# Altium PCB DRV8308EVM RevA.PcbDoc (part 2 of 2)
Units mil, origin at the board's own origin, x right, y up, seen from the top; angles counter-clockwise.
Board outline 4724.41 x 2952.76 mil, 2 copper layers (Top Layer, Bottom Layer), stack 62 mil thick; 110 components, 81 nets, 346 pads, 592 vias.
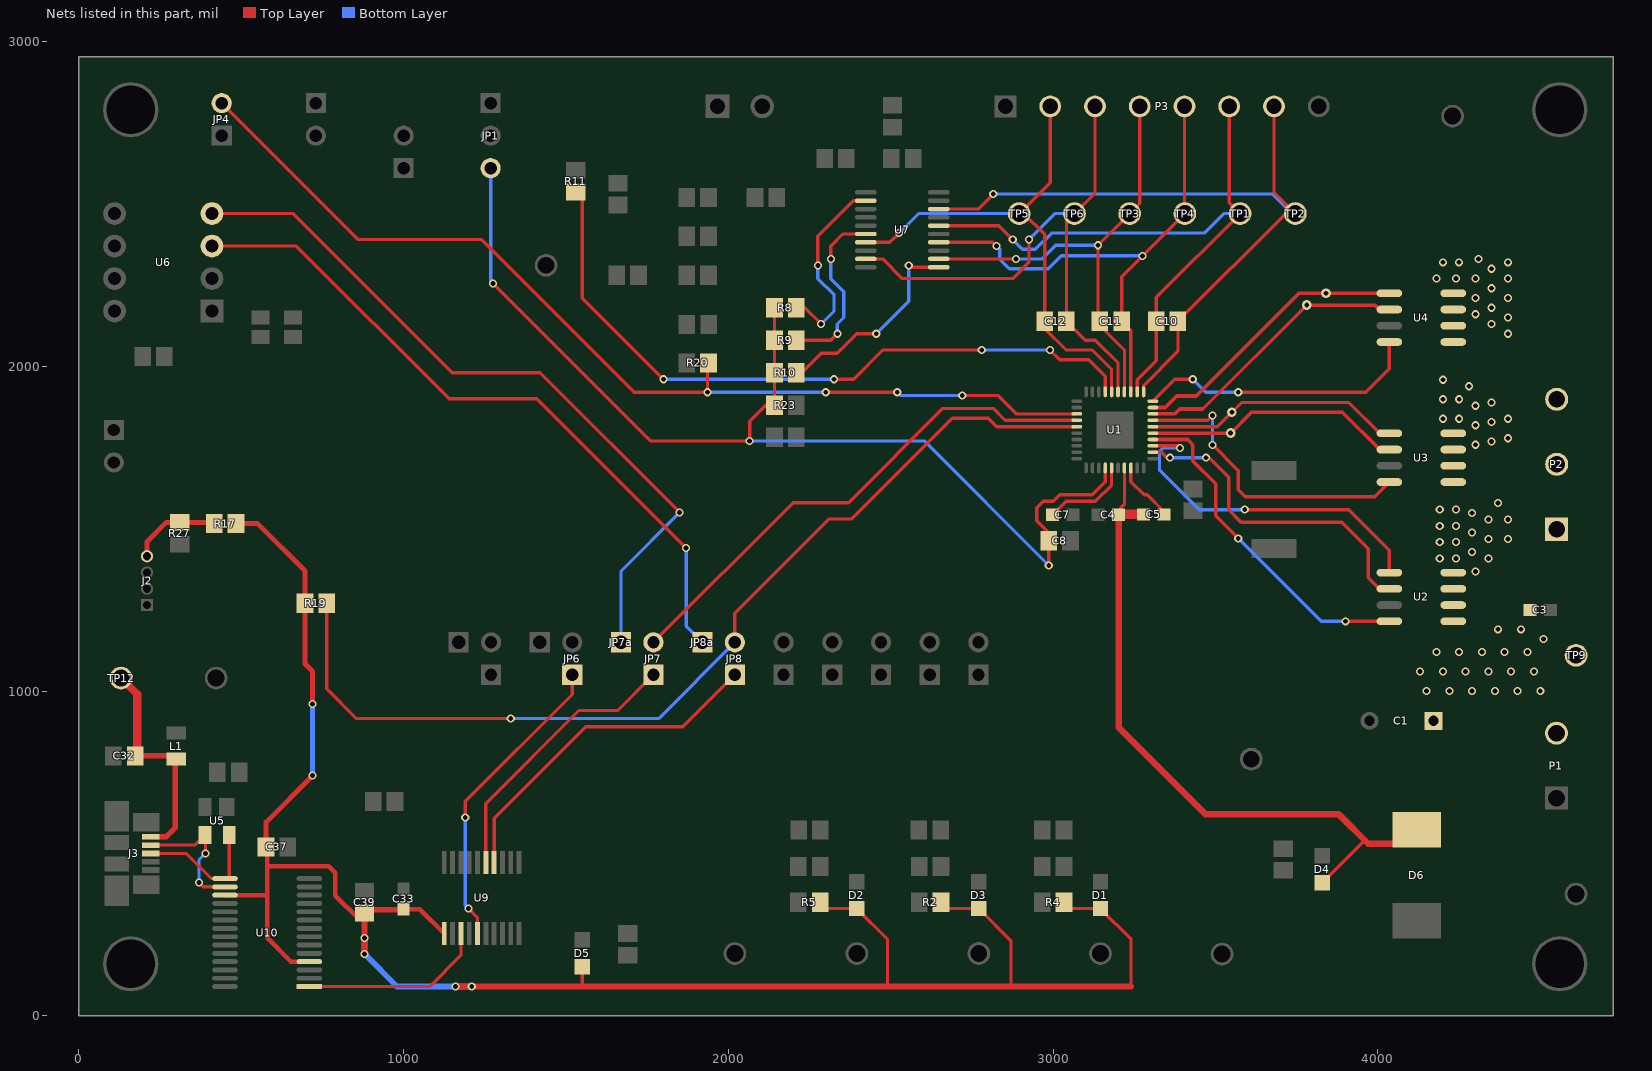
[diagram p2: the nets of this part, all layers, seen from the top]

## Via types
v1: diameter 25, hole 15, Top Layer to Bottom Layer, tented both sides, 582 vias
v2: diameter 25, hole 15, Top Layer to Bottom Layer, tented bottom, 5 vias
v3: diameter 30, hole 15, Top Layer to Bottom Layer, tented bottom, 4 vias
v4: diameter 35, hole 15, Top Layer to Bottom Layer, tented both sides, 1 vias

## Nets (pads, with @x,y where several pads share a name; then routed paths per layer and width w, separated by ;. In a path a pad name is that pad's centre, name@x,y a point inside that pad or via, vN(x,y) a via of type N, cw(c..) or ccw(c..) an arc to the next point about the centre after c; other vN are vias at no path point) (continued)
SCS_MSP430: JP6.1 U9.5 | length 934.6
  Top Layer w10: v1(1190,610) 1190,660 1519.35,989.35 JP6.1@1519.35,1050 ; v1(1200,330) 1227.6,302.4 U9.5@1227.6,253.3
  Bottom Layer w10: 1190,340 v1(1190,610)
SDATAI: JP7.2 U1.14 | length 1616.8
  Top Layer w10: JP7.2@1769.35,1150 2199.35,1580 2370,1580 2660,1870 2815.23,1870 2851.69,1833.54 U1.14@3072.78,1833.54
SDATAI_EEPROM: JP7a.1 U6.4 | length 2295.9
  Top Layer w10: U6.4@410,2470 660,2470 1150,1980 1420,1980 v1(1850,1550)
  Bottom Layer w10: JP7a.1@1669.35,1150 1669.35,1369.35 v1(1850,1550)
SDATAI_MSP430: JP7.1 U9.15 | length 861.4
  Top Layer w10: U9.15@1253.3,472.3 1253.3,653.3 1540,940 1659.35,940 JP7.1@1769.35,1050
SDATAO: JP8.2 R19.1 U1.15 | length 3057.4
  Top Layer w10: R19.1@763.46,1270 763.46,1006.54 855,915 v1(1330,915) ; JP8.2@2020,1150 2020,1240 2310,1530 2380,1530 2690,1840 2800,1840 2826.14,1813.86 U1.15@3072.78,1813.86
  Bottom Layer w10: v1(1330,915) 1785,915 JP8.2@2020,1150
SDATAO_EEPROM: JP8a.1 U6.3 | length 2155.9
  Top Layer w10: U6.3@410,2370 670,2370 1140,1900 1410,1900 v1(1870,1440)
  Bottom Layer w10: v1(1870,1440) 1870,1200 JP8a.1@1920,1150
SDATAO_MSP430: JP8.1 U9.14 | length 1060.2
  Top Layer w10: U9.14@1278.9,472.3 1278.9,608.55 1560.35,890 1860,890 JP8.1@2020,1050
SMODE: JP4.2 R20.2 U1.13 | length 3115.6
  Top Layer w10: JP4.2@440,2810 860,2390 1240,2390 1710,1920 v1(1935.51,1920) R20.2@1935.51,2006.54 ; v1(2300,1920) v1(2520,1920) ; v1(2720,1910) 2830,1910 2886.77,1853.23 U1.13@3072.78,1853.23
  Bottom Layer w10: v1(1935.51,1920) v1(2300,1920) ; v1(2520,1920) 2530,1910 v1(2720,1910)
TX: U9.3 U10.1 | length 573.2
  Top Layer w10: U10.1@710,90 1080,90 1176.4,186.4 U9.3@1176.4,253.3
U: P2.1 U1.33 U2.1 U2.5 U2.6 | length 1088.9
  Top Layer w10: v1@3383.84,1754.8 v1(3390.22,1748.43)
  Top Layer w11: U1.33@3307.03,1754.8 v1@3383.84,1754.8 ; v2(3590,1558.43) 3910.22,1558.43 4035.1,1433.54 U2.1@4035.1,1364.63
  Bottom Layer w10: v1(3390.22,1748.43) 3338.43,1748.43 3327.7,1737.7 3327.7,1680 3449.28,1558.43 v2(3590,1558.43)
U+: R8.2 U7.2 | length 597.7
  Top Layer w10: R8.2@2208.98,2180 2235.51,2180 v1(2285.51,2130) ; v1(2275.51,2310) 2275.51,2400 2385.08,2509.57 U7.2@2423.31,2509.57
  Bottom Layer w10: v1(2275.51,2310) 2275.51,2270 2325.51,2220 2325.51,2170 v1(2285.51,2130)
UH+: C10.2 P3.7 TP2.1 U1.1 U7.18 | length 2258.6
  Top Layer w10: U7.18@2647.72,2483.98 2769.49,2483.98 v1(2815.51,2530) ; U1.1@3278.49,1921.14 3278.49,1940.3 3384.23,2046.04 C10.2@3384.23,2138.54 3715.69,2470 TP2.1@3745.51,2470 3680,2535.51 P3.7@3680,2800
  Bottom Layer w10: v1(2815.51,2530) 3675.51,2530 3735.51,2470 TP2.1@3745.51,2470
UH-: C10.1 P3.6 TP1.1 U1.2 U7.16 | length 2027.4
  Top Layer w10: U7.16@2647.72,2432.8 2832.72,2432.8 v1(2875.51,2390) ; U1.2@3258.8,1921.14 3258.8,1958.8 3317.3,2017.3 C10.1@3317.3,2138.54 3317.3,2211.79 TP1.1@3575.51,2470 3542.2,2503.31 P3.6@3542.2,2800
  Bottom Layer w10: v1(2875.51,2390) 2905.51,2360 2945.51,2360 2995.51,2410 3465.51,2410 3525.51,2470 TP1.1@3575.51,2470
UHS_GATE: U1.32 U2.2 | length 1013.5
  Top Layer w10: v1@3350.22,1718.43 v1(3360.22,1718.43) ; U2.2@4004.02,1314.63 U2.2@4035.1,1314.63
  Top Layer w11: U1.32@3307.03,1735.12 3333.53,1735.12 v1@3350.22,1718.43 ; v2(3470.22,1718.43) 3480.22,1718.43 3540.22,1658.43 3540.22,1558.43 3578.65,1520 3888.65,1520 3970.22,1438.43 3970.22,1348.43 U2.2@4004.02,1314.63
  Bottom Layer w11: v1(3360.22,1718.43) v2(3470.22,1718.43)
ULS_GATE: U1.34 U2.4 | length 1047
  Top Layer w11: U1.34@3307.03,1774.49 3414.16,1774.49 3430.22,1758.43 3430.22,1708.43 3500.22,1638.43 3500.22,1539.78 v2(3570,1470) ; v1(3900,1214.63) U2.4@4035.1,1214.63
  Bottom Layer w11: v2(3570,1470) 3825.37,1214.63 v1(3900,1214.63)
USB5V: C32.2 J3.1 L1.1 TP12.1 | length 668.7
  Top Layer w17: C32.2@173.46,800 L1.1@290,800 ; J3.1@221.61,551.18 268.82,551.18 297.64,580 L1.1@297.64,790
  Top Layer w25: TP12.1@130,1040 180,990 C32.2@180,806.54
USBDM: J3.2 U5.3 U10.16 | length 418.8
  Top Layer w10: J3.2@221.61,525.59 357.4,525.59 U5.3@388.5,556.69 ; v1(370,410) 382.91,397.09 U10.16@450.16,397.09 ; v1(390,500) U5.3@390,555.2
  Bottom Layer w10: v1(370,410) 370,480 v1(390,500)
USBDP: J3.3 U5.4 U10.15 | length 394.4
  Top Layer w10: J3.3@221.61,500 330,500 407.32,422.68 U10.15@450.16,422.68 ; U10.15@463.31,422.88 U5.4@463.31,556.69
V: P2.2 U1.36 U3.1 U3.5 U3.6 | length 798.3
  Top Layer w10: U1.36@3307.03,1813.86 3505.66,1813.86 3580.22,1888.43 3910.22,1888.43 4005.22,1793.43 U3.1@4035.1,1793.43
  other v3: 3550.22,1858.43
V3P3: C33.1 C37.2 C39.1 D1.1 D2.1 D3.1 D5.1 R2.2 R4.2 R5.2 R17.2 R19.2 U9.1 U10.4 U10.17 | length 6232.7
  Top Layer w10: 1550,90 D5.1@1550,151.12 ; R5.2@2301.8,330.25 D2.1@2395.59,330.25 2490,235.84 2490,90 ; R2.2@2674.33,330.44 D3.1@2771.11,330.44 2870,231.55 2870,90 ; R4.2@3052.9,330.25 D1.1@3145.59,330.25 3240,235.84 3240,90
  Top Layer w14: U10.17@450.16,371.5 580,371.5 ; C37.2@580,516.54 580,460 ; U10.4@710,166.77 653.23,166.77 580,240 580,371.5 ; C39.1@860,300 790,370 790,440 770,460 580,460 ; C33.1@1000,328.5 1050,328.5 U9.1@1125.2,253.3 ; 580,371.5 580,460
  Top Layer w15: R17.2@484.09,1515.59 550.94,1515.59 696.54,1370 R19.2@696.54,1270 696.54,1083.46 720,1060 v1(720,960) ; C37.2@576.54,520 576.54,596.54 v1(720,740)
  Top Layer w18: v1(880,190) v1(880,240) 880,326.54 C33.1@988.03,326.54 ; v1(1160,90) v1(1210,90) 1550,90 2870,90 3240,90
  Bottom Layer w15: v1(720,740) v1(720,960)
  Bottom Layer w18: v1(880,240) v1(880,190) 980,90 v1(1210,90)
V3P3X: J2.4 R17.1 R27.1 | length 273.2
  Top Layer w15: J2.4@210,1415 210,1460 269.06,1519.06 R27.1@310.63,1519.06 R17.1@413.7,1519.06
V+: R9.2 U7.6 | length 552.9
  Top Layer w10: R9.2@2208.98,2080 2315.51,2080 v1(2335.51,2100) ; v1(2315.51,2330) 2315.51,2370 2352.72,2407.2 U7.6@2423.31,2407.2
  Bottom Layer w10: v1(2315.51,2330) 2315.51,2270 2355.51,2230 2355.51,2150 2335.51,2130 v1(2335.51,2100)
VCP: C5.1 U1.28 | length 182.5
  Top Layer w10: U1.28@3239.12,1686.89 3239.12,1644.8 3279.91,1604.02 3290.08,1604.02 C5.1@3341.4,1552.7
VH+: C11.2 P3.5 TP4.1 U1.3 U7.14 | length 1667.3
  Top Layer w10: U7.14@2647.72,2381.61 2813.9,2381.61 v1(2825.51,2370) ; U1.3@3239.12,1921.14 3239.12,2110.35 C11.2@3210.92,2138.54 3210.92,2275.41 v1(3275.51,2340) TP4.1@3405.51,2470 3404.41,2471.1 P3.5@3404.41,2800
  Bottom Layer w10: v1(2825.51,2370) 2835.51,2360 2835.51,2330 2865.51,2300 2985.51,2300 3025.51,2340 v1(3275.51,2340)
VH-: C11.1 P3.4 TP3.1 U1.4 U7.12 | length 1444.6
  Top Layer w10: U7.12@2655.51,2330.43 2885.08,2330.43 v1(2885.51,2330) ; C11.1@3138.05,2144.49 v1(3138.05,2372.54) TP3.1@3235.51,2470 3266.61,2501.1 P3.4@3266.61,2800 ; C11.1@3144,2125.44 3219.43,2050 U1.4@3219.43,1921.14
  Bottom Layer w10: v1(2885.51,2330) 2965.51,2330 3008.05,2372.54 v1(3138.05,2372.54)
VHS_GATE: U1.35 U3.2 | length 802.3
  Top Layer w10: U3.2@4005.22,1743.43 U3.2@4035.1,1743.43
  Top Layer w11: U1.35@3307.03,1794.17 v3(3546.51,1794.17) 3610.77,1858.43 3890.22,1858.43 U3.2@4005.22,1743.43
VINT: C7.1 U1.25 | length 272.3
  Top Layer w10: C7.1@2998.41,1542.7 3039.73,1584.02 3129.91,1584.02 3180.06,1634.17 U1.25@3180.06,1686.89
VLS_GATE: U1.37 U3.4 | length 943.8
  Top Layer w10: v2(3490.77,1757.88) 3570,1678.65
  Top Layer w11: U1.37@3307.03,1833.54 3475.89,1833.54 v1(3490.77,1848.43) ; 3570,1678.65 3570,1620 3591.57,1598.43 3990.1,1598.43 U3.4@4035.1,1643.43
  Bottom Layer w10: v2(3490.77,1757.88) v1(3490.77,1848.43)
VM: C1.1 C3.1 C4.1 C5.2 D4.1 D6.2 P1.2 TP9.1 U1.27 U2.7 U2.8 U3.7 U3.8 U4.7 U4.8 | length 2089.9
  Top Layer w10: C4.1@3201.4,1542.7 3202.72,1544.02 C4.1@3215.43,1556.73 ; C4.1@3201.4,1556.46 3219.43,1574.49 U1.27@3219.43,1686.89 ; D4.1@3828.24,409.8 3959.22,540.78
  Top Layer w20: C4.1@3201.4,1542.7 3201.4,888.6 3470,620 3880,620 3970,530 D6.2@4070,530
  Top Layer w30: C4.1@3202.72,1544.02 C5.2@3278.41,1544.02
  other v1: 4150,1000 4220,1000 4290,1000 4360,1000 4430,1000 4500,1000 4130,1060 4200,1060 4270,1060 4340,1060 4410,1060 4480,1060 4180,1120 4250,1120 4320,1120 4390,1120 4460,1120 4510,1160 4370,1190 4440,1190 4300.22,1368.43 4190.22,1408.43 4240.22,1408.43 4340.22,1408.43 4290.22,1428.43 4190.22,1458.43 4240.22,1458.43 4340.22,1468.43 4400.22,1468.43 4290.22,1488.43 4190.22,1508.43 4240.22,1508.43 4340.22,1528.43 4400.22,1528.43 4290.22,1548.43 4190.22,1558.43 4240.22,1558.43 4370.22,1578.43 4300.22,1758.43 4350.22,1768.43 4400.22,1778.43 4300.22,1818.43 4350.22,1828.43 4200.22,1838.43 4250.22,1838.43 4400.22,1838.43 4300.22,1878.43 4350.22,1888.43 4200.22,1898.43 4250.22,1898.43 4280.22,1938.43 4200.22,1958.43 4400,2100 4350,2130 4400,2150 4300,2160 4350,2180 4300,2210 4400,2210 4350,2240 4180,2270 4240,2270 4300,2270 4400,2270 4350,2300 4200,2320 4250,2320 4400,2320 4310,2330
VREG: C8.2 JP1.3 R8.1 R9.1 R10.1 R23.2 U1.24 | length 3332
  Top Layer w10: v1(1275,2255) 1760,1770 v1(2065.51,1770) 2065.51,1830 2115.51,1880 R23.2@2142.05,1880 R10.1@2142.05,1980 ; R10.1@2142.05,1996.54 R9.1@2142.05,2080 R8.1@2142.05,2180 ; v1(2986.44,1386.44) C8.2@2986.44,1462.7 ; C8.2@2992.11,1481.81 2949.91,1524.02 2949.91,1564.02 2969.91,1584.02 2999.91,1584.02 3019.91,1604.02 3119.91,1604.02 3160.38,1644.49 U1.24@3160.38,1686.89
  Bottom Layer w10: JP1.3@1268.03,2610 1268.03,2261.97 v1(1275,2255) ; v1(2065.51,1770) 2602.88,1770 v1(2986.44,1386.44)
VSW: R11.2 U1.7 | length 2159.5
  Top Layer w10: R11.2@1550,2536.54 1550,2210 v1(1800,1960) ; v1(2325.51,1960) 2385.51,1960 2475.51,2050 v1(2780,2050) ; v1(2990,2050) 3020,2020 3110,2020 3160.38,1969.62 U1.7@3160.38,1921.14
  Bottom Layer w10: v1(1800,1960) v1(2325.51,1960) ; v1(2780,2050) v1(2990,2050)
W: P2.3 U1.39 U4.1 U4.5 U4.6 | length 873.8
  Top Layer w11: U1.39@3307.03,1872.91 3344.71,1872.91 3380.22,1908.43 3440.77,1908.43 3756.97,2224.63 3880.22,2224.63 U4.1@4035.1,2224.63
  other v3: 3840,2224.63
W+: R10.2 U7.11 | length 635
  Top Layer w10: R10.2@2208.98,1980 2225.51,1980 2285.51,2040 2335.51,2040 2395.51,2100 v1(2455.51,2100) ; v1(2555.51,2310) 2560.67,2304.84 U7.11@2640.67,2304.84
  Bottom Layer w10: v1(2455.51,2100) 2555.51,2200 v1(2555.51,2310)
WH+: C12.2 P3.3 TP6.1 U1.5 U7.9 | length 1790
  Top Layer w10: U7.9@2423.31,2330.43 2475.08,2330.43 2535.51,2270 2875.51,2270 2925.51,2320 v1(2925.51,2390) ; P3.3@3128.82,2800 3128.82,2533.31 TP6.1@3065.51,2470 3040.92,2445.41 C12.2@3040.92,2138.54 3099.47,2080 3130,2080 3199.75,2010.25 U1.5@3199.75,1921.14
  Bottom Layer w10: v1(2925.51,2390) 3005.51,2470 TP6.1@3065.51,2470
WH-: C12.1 P3.2 TP5.1 U1.6 U7.7 | length 1577.9
  Top Layer w10: U7.7@2423.31,2381.61 2497.13,2381.61 v1(2525.51,2410) ; C12.1@2974,2116 3040,2050 3120,2050 3180.06,1989.94 U1.6@3180.06,1921.14 ; C12.1@2974,2138.54 2974,2406 2910,2470 TP5.1@2895.51,2470 2991.02,2565.51 P3.2@2991.02,2800
  Bottom Layer w10: v1(2525.51,2410) 2585.51,2470 TP5.1@2895.51,2470
WHS_GATE: U1.38 U4.2 | length 872.6
  Top Layer w10: 3460.77,1868.43 v3(3780.77,2188.43) ; U4.2@4004.02,2174.63 U4.2@4035.1,2174.63
  Top Layer w11: U1.38@3307.03,1853.23 3375.03,1853.23 3390.22,1868.43 3460.77,1868.43 ; v3(3780.77,2188.43) 3990.22,2188.43 U4.2@4004.02,2174.63
WLS_GATE: U1.40 U4.4 | length 884.6
  Top Layer w11: U1.40@3307.03,1892.6 3374.43,1960 v1(3430,1960) ; v2(3570,1920) 3962.34,1920 4035.1,1992.76 U4.4@4035.1,2074.63
  Bottom Layer w11: v1(3430,1960) 3470,1920 v2(3570,1920)
pads on no net: J3.4 U6.7 U7.3 U7.5 U7.15 U7.17 U9.2 U9.6 U10.2 U10.3 U10.6 U10.8 U10.9 U10.10 U10.11 U10.12 U10.13 U10.14 U10.19 U10.22 U10.23 U10.24 U10.27 U10.28

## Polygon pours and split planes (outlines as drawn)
GND on Bottom Layer "Bottom GND plane" (solid, remove dead copper, pour order 7): 0,0 4724.41,0 4724.41,2952.76 0,2952.76
GND on Top Layer "Top GND plane" (solid, remove dead copper, pour order 4): 0,0 4724.41,0 4724.41,2952.76 0,2952.76

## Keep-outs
Keep-Out Layer:
  lines w10: -5,0 ccw(c0,0) 0,-5 ; -5,0 ccw(c0,0) 0,-5 ; -5,0 ccw(c0,0) 0,-5 ; -5,0 ccw(c0,0) 0,-5 ; -5,0 ccw(c0,0) 0,-5 ; -5,0 ccw(c0,0) 0,-5
  lines w19.68: -9.84,0 ccw(c0,0) 0,-9.84 ; -9.84,0 ccw(c0,0) 0,-9.84 ; -9.84,0 -9.84,2952.76 ; -9.84,2952.76 cw(c0,2952.76) 0,2962.6 ; -9.84,2952.76 cw(c0,2952.76) 0,2962.6 ; 0,-9.84 4724.41,-9.84 ; 0,2962.6 4724.41,2962.6 ; 4724.41,-9.84 ccw(c4724.41,0) 4734.25,0 ; 4724.41,-9.84 ccw(c4724.41,0) 4734.25,0 ; 4724.41,2962.6 cw(c4724.41,2952.76) 4734.25,2952.76 ; 4724.41,2962.6 cw(c4724.41,2952.76) 4734.25,2952.76 ; 4734.25,0 4734.25,2952.76
  text ".Layer_Name" at 577,-858.49 h60

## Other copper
Top Layer:
  region net VM: 4258.86,2163.3 4414.81,2075.58 4413.49,2349.24 4349,2350.75 4244.77,2349.86 4163.52,2349.26 4163.52,2231.62 4199.93,2164.7
  region net VM: 4041.87,516.13 4195.5,515.26 4287.5,694.06 4411.95,786.23 4587.06,825.21 4649.24,1091.74 4649.22,1136.61 4510.04,1206.89 4483.97,1236.82 4438.43,1278.55 4346.86,1202.47 4267.29,1168.03 4164.67,1167.83 4114.24,1117.03 4113.3,942.03 4096.73,800.79 4051.76,676.12
  region net W: 4006.57,2234.88 4122.9,2234.88 4163.62,2185.35 4181.8,2156.34 4193.63,2143.67 4205.47,2136.17 4263.44,2135.42 4263.44,2061.48 4172.2,2061.48 4120.44,2136.77 4096.83,2174.8 4085.29,2195.6 4067.48,2210.49 4002.68,2211.96
  region net V: 4006.57,1804.88 4122.9,1804.88 4163.62,1755.35 4181.8,1726.34 4193.63,1713.67 4205.47,1706.17 4263.44,1705.42 4263.67,1629.29 4176.64,1625.49 4120.44,1706.77 4096.83,1744.8 4085.29,1765.6 4067.48,1780.49 4002.68,1781.96
  region net U: 4006.57,1374.88 4122.9,1374.88 4163.62,1325.35 4181.8,1296.34 4193.63,1283.67 4205.47,1276.17 4263.44,1275.42 4263.44,1201.48 4172.2,1201.48 4120.44,1276.77 4096.83,1314.8 4085.29,1335.6 4067.48,1350.49 4002.68,1351.96
  region net VM: 4205.95,1732.88 4193.09,1741.46 4163.79,1790.41 4164.05,2011.1 4414.71,1893.78 4415.64,1763.04 4263.18,1732.11
  region net VM: 4240.75,1302.54 4264.65,1302.54 4414.82,1460.67 4414.78,1603.51 4164.12,1590.95 4163.85,1356.84 4198.71,1303.94
  region net ISENSE: 4029.45,1253.44 4029.19,1253.18 4000.98,1253.18 3967.35,1235.32 3927.88,1235.32 3905.08,1242.91 3851.83,1247.15 3804.11,1303.16 3777.51,1351.69 3772.48,1371.05 3772.48,1492.98 3873.95,1492.98 3926.33,1446.98 3935.81,1439.7 3941.38,1432.57 3944.07,1408.69 3943.42,1372.54 3951.92,1336.28 3973.6,1302.25 4007.37,1276.08
  region net ISENSE: 4007.5,1682.15 3976.85,1664.07 3931.6,1625.35 3784.48,1625.55 3665.48,1625.55 3610,1630 3599.29,1699.74 3597.02,1726.84 3609.18,1804.82 3625.99,1816.21 3870.36,1827.96 3909.21,1808.29 3971.57,1725.3 4008.56,1704.99
  region net ISENSE: 4008.52,2136.21 3974.04,2161.93 3826.03,2161.93 3806.54,2145.65 3790.24,2111.54 3775.45,2048.1 3774.15,1944.05 3949.86,1944.21 3970.64,1965.72 3973.71,2046.8 3979.09,2088.18 3984.66,2097.22 4007.92,2113.22
  region net U: 4256.81,1276.41 4277.94,1286.82 4513.54,1540.16 4594.28,1540.15 4594.26,1455.59 4422.1,1292.23 4351.5,1231.81 4266.02,1186.23 4165.48,1186.82 4164.29,1248.28
  region net V: 4204.53,1703.76 4547.81,1742.82 4594.73,1742.82 4594.73,1658.82 4322.01,1621.72 4176.76,1613.37
  region net W: 4166.5,2057.62 4534.23,1855.38 4595.09,1855.09 4593.75,1930.53 4429.96,2049.16 4262.29,2136.49 4228.44,2137.5 4166.5,2108.04
  text ".Layer_Name" at 577,-858.49 h60
Bottom Layer:
  region net VM: 4163.18,2350 4163.18,1137.74 4414.7,1137.74 4414.7,2350
  region net VM: 4411.06,1257.33 4497.82,1221.76 4545.24,1187.27 4648.69,1136.27 4648.83,1091.15 4617.89,968.85 4594.2,886.44 4585.64,826.27 4135.24,876.39 4114.02,1033.26 4114.59,1117.36 4163.15,1166.7
  region net ISENSE: 4108.01,2262 4153.28,2262.31 4153.52,1189.26 3993.81,1197.63 3967.35,1235.35 3927.72,1235.18 3905.5,1243.32 3851.96,1246.89 3804.73,1302.74 3777.51,1351.81 3772.59,1371.16 3772.34,1571.25 3729.15,1609.96 3611.67,1630.43 3604.13,1665.46 3599.91,1700.36 3597.02,1726.84 3613.63,1810.93 3746.57,1818.3 3771.54,1838.25 3773.85,1888.04 3775.12,2047.77 3790.11,2111.14 3806.53,2145.63 3824.96,2162 3872.06,2162 3898.03,2182.27 3925.39,2260.44
  text ".Layer_Name" at 577,-858.49 h60

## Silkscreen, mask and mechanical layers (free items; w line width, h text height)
Top Overlay:
  text "HALL" at 3907.23,2881.54 h70
  text "FG" at 2193.79,2880.79 h70
  text "INPUT" at 2193.79,2825.68 h70
  text "INPUT" at 3907.24,2825.68 h70
  text "CURRENT" at 1378.03,2745.7 h55
  text "]" at 1338.03,2720 h180
  text "GND" at 4163.51,2652.88 h70
  text "5V" at 1095.16,2639.36 h60
  text "_" at 1941.09,2632.48 h100
  text "]" at 1053.72,2617.55 h180
  text "[" at 1167.04,2617.55 h180
  text "_" at 3015.06,2616.5 h55
  text "_" at 3283.2,2616.5 h55
  text "_" at 3559.94,2616.5 h55
  text "DIFF" at 664.19,2602.79 h70
  text "SMODE" at 327.82,2602.01 h70
  text "HPWR" at 3751.23,2598.8 h50
  text "HGND" at 2790.13,2598.26 h50
  text "W" at 2960.75,2592.42 h60
  text "W" at 3096.86,2592.42 h60
  text "V" at 3243.84,2592.42 h60
  text "V" at 3380.16,2592.42 h60
  text "U" at 3521.27,2592.42 h60
  text "U" at 3655.88,2592.42 h60
  text "+" at 3150.87,2589.61 h70
  text "+" at 3419.22,2589.61 h70
  text "+" at 3694.24,2589.61 h70
  text "+" at 2081.93,2587.35 h100
  text "HALL" at 649.78,2549.76 h70
  text "HALL POWER" at 939.81,2503.74 h70
  text "W" at 4087.75,2258.24 h110
  text "W" at 3788.38,2211.55 h40
  text "GND" at 1372.45,2194.43 h70
  text "WHSG" at 3651.62,2174.59 h40
  text "WLSG" at 3590,1910 h40
  text "V" at 3569.69,1846.05 h40
  text "V" at 4102.19,1826.51 h110
  text "CLKIN" at 166.89,1788.96 h80
  text "VHSG" at 3425.69,1780.4 h40
  text "VLSG" at 3507.16,1743.19 h40
  text "UHSG" at 3487.81,1705.14 h40
  text "GND" at 166.92,1670 h80
  text "U" at 3550.99,1544.55 h40
  text "DRV8308EVM" at 850,1510 h100
  text "ULSG" at 3489.06,1426.59 h40
  text "U" at 4104.59,1400.86 h110
  text "SCLK" at 1286.35,1216 h60 r90
  text "SCS" at 1536.35,1216 h60 r90
  text "SDATAI" at 1786.35,1216 h60 r90
  text "SDATAO" at 2036.35,1216 h60 r90
  text "CLKIN" at 2186.35,1216 h60 r90
  text "BRAKE" at 2336.35,1216 h60 r90
  text "DIR" at 2486.35,1216 h60 r90
  text "ENABLE" at 2636.35,1216 h60 r90
  text "RESET" at 2786.35,1216 h60 r90
  text "USB5V" at 36.41,1109.99 h80
  text "GND" at 346.96,1110 h80
  text "VM" at 4565.23,990.73 h70
  text "EEPROM" at 1186.35,866 h60 r90
  text "MCU" at 1286.35,866 h60 r90
  text "EEPROM" at 1436.35,866 h60 r90
  text "MCU" at 1536.35,866 h60 r90
  text "EEPROM" at 1686.35,866 h60 r90
  text "MCU" at 1786.35,866 h60 r90
  text "EEPROM" at 1936.35,866 h60 r90
  text "MCU" at 2036.35,866 h60 r90
  text "MCU" at 2186.35,866 h60 r90
  text "MCU" at 2336.35,866 h60 r90
  text "MCU" at 2486.35,866 h60 r90
  text "MCU" at 2636.35,866 h60 r90
  text "MCU" at 2789.22,866 h60 r90
  text "GND" at 3543.51,672.11 h70
  text "GND" at 4543.51,450.45 h70
  text "VM" at 3777.05,320 h80
  text "REV.A" at 4240,80 h60
  text "V3P3" at 1463.89,60.94 h80
  text "GND" at 1943.97,60.94 h80
  text "FGOUT" at 2273.72,60.94 h80
  text "FAULTn" at 2637.01,60.94 h80
  text "LOCKn" at 3027.5,60.94 h80
  text "ENABLE" at 3377.19,60 h80
  text ".Layer_Name" at 577,-858.49 h60
Bottom Overlay:
  text ".Layer_Name" at 577,-858.49 h60
Top Paste:
  text ".Layer_Name" at 577,-858.49 h60
Bottom Paste:
  text ".Layer_Name" at 577,-858.49 h60
Top Solder:
  text ".Layer_Name" at 577,-858.49 h60
  text ".Layer_Name" at 577,-858.49 h60
Bottom Solder:
  text ".Layer_Name" at 577,-858.49 h60
Drill Guide:
  text ".Layer_Name" at 577,-858.49 h60
M1 Board Outline:
  the board outline again, w10
  text ".Layer_Name" at 577,-858.49 h60
M2 Board Dimensions:
  rectangle: 124.5,-410.5 499.5,-285.5
  rectangle: -0.5,-285.5 124.5,-160.5
  lines w7: -0.5,-285.5 999.5,-285.5 ; 124.5,-410.5 124.5,-160.5 ; 249.5,-410.5 249.5,-160.5 ; 499.5,-410.5 499.5,-160.5 ; 749.5,-410.5 749.5,-160.5 ; -0.5,-410.5 -0.5,-160.5 999.5,-160.5 999.5,-410.5 -0.5,-410.5
  lines w10: -0.5,-475.5 -0.5,-455.5 ; 59.5,-485.5 -0.5,-465.5 ; 59.5,-445.5 -0.5,-465.5 ; 223.58,-465.5 -0.5,-465.5 ; 775.42,-465.5 999.5,-465.5 ; 939.5,-485.5 999.5,-465.5 ; 939.5,-445.5 999.5,-465.5 ; 999.5,-475.5 999.5,-455.5
  text "1000 (mil)" at 233.58,-501.49 h60
  text ".Layer_Name" at 577,-858.49 h60
M3 3D STEP Top:
  text ".Layer_Name" at 577,-858.49 h60
M4 3D STEP Bottom:
  text ".Layer_Name" at 577,-858.49 h60
M5 Assembly Top:
  lines w10: -292,-930.17 6308,-930.17 ; -292,-726.83 6310,-726.83 ; -292,-523.5 -292,-1133.5 3713,-1133.5 6310,-1133.5 6310,-523.5 -291.5,-523.5 -291.5,-1133.5 1284,-1133.5 ; 2173,-1133.5 2173,-523.5 ; 3440,-726.83 3440,-523.5 ; 4280,-726.83 4280,-523.5 ; 4902,-1140 4902,-937.17
  text "COMPONENTS MARKED 'DNP' SHOULD NOT BE POPULATED." at 1153.5,-318.5 h60
  text "ASSEMBLY VARIANT:" at 1153,-434 h60
  text ".VariantName" at 2189,-434 h60
  text "PCB VIEWED FROM TOP SIDE" at -228.5,-655.67 h60
  text "BOARD #:" at 2248,-655.67 h60
  text ".PRJ_Number" at 2793.5,-655.67 h60
  text "REV:" at 3638,-655.67 h60
  text ".PCB_Rev" at 3929.5,-655.67 h60
  text "SVN REV:" at 4476,-655.67 h60
  text ".VersionControl_RevNumber" at 4982,-655.67 h60
  text "IGNORE ->" at -228.5,-858.49 h60
  text "PLOT NAME =" at -228.5,-1064.34 h60
  text ".plot_File_Name" at 577,-1064.34 h60
  text "GENERATED    :" at 2250,-1064.34 h60
  text ".Print_Date" at 3119.5,-1064.34 h60
  text ".Print_Time" at 3848.5,-1064.34 h60
  text "TEXAS INSTRUMENTS" at 5113,-1064.34 h60
M6 Assembly Bottom:
  lines w10: -292.5,-727.33 6309.5,-727.33 ; -290.5,-930.67 6309.5,-930.67 ; 1115.5,-1140.5 1115.5,-937.67 ; 1737.5,-727.33 1737.5,-524 ; 2577.5,-727.33 2577.5,-524 ; 3844.5,-1134 3844.5,-524 ; 4733.5,-1134 6309,-1134 6309,-524 -292.5,-524 -292.5,-1134 2304.5,-1134 6309.5,-1134 6309.5,-524
  text "COMPONENTS MARKED 'DNP' SHOULD NOT BE POPULATED." at 6102,-318 h60
  text ".VariantName" at 5058,-434 h60
  text "ASSEMBLY VARIANT:" at 6097,-434 h60
  text ".VersionControl_RevNumber" at 1035.5,-656.17 h60
  text "SVN REV:" at 1541.5,-656.17 h60
  text ".PCB_Rev" at 2088,-656.17 h60
  text "REV:" at 2379.5,-656.17 h60
  text ".PRJ_Number" at 3224,-656.17 h60
  text "BOARD #:" at 3769.5,-656.17 h60
  text "PCB VIEWED FROM BOTTOM SIDE" at 6246,-656.17 h60
  text "IGNORE ->" at 2547.85,-858.49 h60
  text "TEXAS INSTRUMENTS" at 904.5,-1064.84 h60
  text ".Print_Time" at 2169,-1064.84 h60
  text ".Print_Date" at 2898,-1064.84 h60
  text "GENERATED    :" at 3767.5,-1064.84 h60
  text ".plot_File_Name" at 5440.5,-1064.84 h60
  text "PLOT NAME =" at 6246,-1064.84 h60
M9 Title Sheet:
  drawing of 57 lines, arcs and shapes, not listed
  text "1" at 739.84,8036.5 h70
  text "2" at 3235.5,8036.5 h70
  text "3" at 5724.84,8036.5 h70
  text "4" at 8231.51,8036.5 h70
  text "5" at 10730.5,8036.5 h70
  text "6" at 13235.5,8036.5 h70
  text "A" at -416.5,6893.5 h70
  text "A" at 14383.5,6893.5 h70
  text "B" at -416.5,4513.5 h70
  text "B" at 14383.5,4513.5 h70
  text "C" at -416.5,2138.5 h70
  text "C" at 14383.5,2138.5 h70
  text "PROJECT TITLE:" at 11343.5,277.5 h45
  text ".PRJ_Title" at 11393.5,144.17 h70
  text "DESIGNED FOR:" at 11343.5,-23.5 h45
  text ".PRJ_Customer" at 11393.5,-163.5 h70
  text "D" at -416.5,-231.5 h70
  text "D" at 14383.5,-231.5 h70
  text "FILE NAME:" at 11343.5,-323.5 h45
  text ".PCB_File_Name_No_Path" at 11393.5,-443.5 h70
  text "Texas Instruments (TI) and/or its licensors do not warrant the accuracy or completeness of this specification" at 6374,-605.34 h45
  text "ENGINEER:" at 11343.5,-613.5 h45
  text "LAYOUT BY:" at 12848.5,-613.5 h45
  text "or any information contained therein. TI and/or its licensors do not warrant that this design will meet" at 6329.01,-718 h45
  text ".PRJ_Engineer" at 11393.5,-768.49 h70
  text ".PCB_Layout" at 12899,-768.49 h70
  text "the specifications, will be suitable for your application or fit for any particular purpose, or will operate in" at 6329.01,-830.67 h45
  text ".Layer_Name" at 577,-858.49 h60
  text "ALTIUM DESIGNER VERSION:" at 12848.5,-923.5 h45
  text "an implementation. TI and/or its licensors do not warrant that the design is production worthy. You should" at 6329.01,-943.33 h45
  text "completely validate and test your design implementation to confirm the system functionality for your application." at 6374,-1056 h45
  text ".print_Scale" at 11393.5,-1056.83 h70
  text ".Application_BuildNumber" at 12899,-1056.83 h70
  text "1" at 739.84,-1263.5 h70
  text "2" at 3235.5,-1263.5 h70
  text "3" at 5724.84,-1263.5 h70
  text "4" at 8231.51,-1263.5 h70
  text "5" at 10730.5,-1263.5 h70
  text "6" at 13235.5,-1263.5 h70
M10 Fab Notes:
  drawing of 213 lines, arcs and shapes, not listed
  text "DESIGN INFORMATION" at 12381.02,6810 h60
  text "(REFER ALSO ARRAY/PANEL PROFILING INFORMATION)" at 12019.46,6648.29 h60
  text "BOARD SIZE" at 11333.46,6644 h60
  text "4724.4MIL" at 11795.78,6516.18 h60
  text "X" at 12301.46,6516.18 h60
  text "2952.8MIL" at 12532.78,6516.18 h60
  text "Number of Layers :" at 11736.46,6319 h60
  text "2" at 12831.27,6309 h60
  text "MIN. TRACK WIDTH:" at 11736.46,6180 h60
  text "10" at 12810,6180 h60
  text "MIL" at 12987.46,6180 h60
  text "MIN. CLEARANCE:" at 11736.46,6048 h60
  text "8" at 12832.7,6048 h60
  text "MIL" at 12987.46,6048 h60
  text "MIN. VIA PAD SIZE:" at 11736.46,5916 h60
  text "25" at 12802.71,5916 h60
  text "MIL" at 12987.46,5916 h60
  text "5" at 12830,5780 h60
  text "MIL" at 12990,5780 h60
  text "MIN. ANNULAR RING:" at 11736.48,5770.02 h60
  text "PER" at 11607.23,5652 h60
  text "IPC-D-275 CLASS 2 LEVEL C" at 11827.23,5652 h60
  text "MIL, HOLES" at 13315.46,5539.71 h60
  text "+/-" at 12923,5539 h60
  text "+/-" at 13777,5539 h60
  text "REGISTRATION TOLERANCES:" at 11407.23,5534 h60
  text "METAL" at 12607,5534 h60
  text "5" at 13183.2,5534 h60
  text "3" at 14016.2,5534 h60
  text "MIL" at 14132.46,5534 h60
  text "MATERIAL:" at 11332.46,5324.54 h60
  text "FR-4 High Tg" at 12318.9,5184.21 h60
  text "FR-408" at 11753.46,5175.64 h60
  text "X" at 12165.46,5175.64 h60
  text "OTHER" at 13241.46,5175.64 h60
  text "62 MIL (1.6mm) +/-10%" at 12073.56,5012.92 h60
  text "THICKNESS:" at 11407.23,5008.64 h60
  text "X" at 11945.4,5008.64 h60
  text "OTHER" at 13358.46,5008.64 h60
  text "TOLERANCE:" at 11407.23,4850.64 h60
  text "X" at 12246.53,4850.64 h60
  text "ANSI IPC-6012 TYPE 3 CLASS 2" at 12433.48,4850.64 h60
  text "OTHER +/-" at 12433.46,4694.64 h60
  text "BOW & TWIST:" at 11407.23,4537.64 h60
  text "X" at 12246.53,4537.64 h60
  text "ANSI IPC-6012 TYPE 3 CLASS 2" at 12433.48,4537.64 h60
  text "OTHER +/-" at 12433.46,4379.13 h60
  text "COPPER THICKNESS (FINISHED):" at 11332.46,4243.64 h60
  text "1.4MIL (1oz)" at 12212.46,4090.92 h60
  text "2MIL (1.4oz)" at 12979.46,4090.92 h60
  text "2.8MIL (2oz)" at 13706.46,4090.92 h60
  text "OUTER:" at 11689.46,4086.64 h60
  text "X" at 12850,4080 h60
  text "1.4MIL (1oz)" at 12212.46,3933.92 h60
  text "2.8MIL (2oz)" at 12979.46,3933.92 h60
  text "N/A" at 13706,3934.29 h60
  text "INNER SIGNAL:" at 11400.38,3929.64 h60
  text "X" at 13580,3930 h60
  text "DRILLING:" at 11332.46,3790.64 h60
  text "REFERENCE:" at 11407.23,3673.64 h60
  text "X" at 12055.46,3673.64 h60
  text "AS SHOWN" at 12242.46,3673.64 h60
  text "X" at 12956.46,3673.64 h60
  text "NC_DRILL FILES" at 13093.46,3673.64 h60
  text "PTH MIN COPPER THICKNESS:" at 11407.23,3515.64 h60
  text "X" at 12757.46,3515.64 h60
  text "1MIL" at 12894.46,3515.64 h60
  text "OTHER" at 13391.46,3515.64 h60
  text "BOARD FINISH:" at 11332.46,3356.64 h60
  text "SILKSCREEN:" at 11487.68,3238.64 h60
  text "X" at 12436.46,3238.64 h60
  text "TOP" at 12562.46,3238.64 h60
  text "BOTTOM" at 13073.46,3238.64 h60
  text "SILKSCREEN COLOR:" at 11487.68,3071.64 h60
  text "X" at 12435.42,3071.64 h60
  text "WHITE" at 12562.46,3071.64 h60
  text "OTHER" at 13073.46,3071.64 h60
  text "SOLDER RESIST COLOR:" at 11487.68,2901.64 h60
  text "X" at 12055.42,2742.44 h60
  text "GREEN" at 12182.46,2742.44 h60
  text "BLUE" at 12773.46,2742.44 h60
  text "OTHER" at 13311.46,2742.44 h60
  text "IMMERSION GOLD (ENIG)" at 12393.46,2553.92 h60
  text "ENEPIG" at 13731,2550.64 h60
  text "SURFACE FINISH:" at 11332.46,2549.64 h60
  text "X" at 12206.51,2549.64 h60
  text "IMM. TIN/SILVER OR EQUIV" at 11662,2392.64 h60
  text "OTHER" at 13093.46,2392.64 h60
  text "ARRAY/PANEL:" at 11332.46,2213.64 h60
  text "CUT AND TRIM PER MECH LAYER 1" at 12393.46,2209.35 h60
  text "N.C. ROUTE" at 12393.46,2057.64 h60
  text "X" at 13072.46,2057.64 h60
  text "V. SCORE" at 13259.46,2057.64 h60
  text "CERTIFICATION:" at 11332.46,1920.64 h60
  text "MATERIALS AND WORKMANSHIP FOR ALL PCBS" at 12057.46,1920.64 h60
  text "TO MEET OR EXCEED THE REQUIREMENTS OF:" at 12057.46,1822.64 h60
  text "X" at 11683.96,1686.13 h60
  text "ANSI IPC-A-600F CLASS ->" at 11822.96,1686.13 h60
  text "X" at 13462.02,1686.13 h60
  text "2" at 13580.96,1686.14 h60
  text "1" at 13265.96,1684.64 h60
  text "3" at 13934.96,1684.64 h60
  text "X" at 11686.02,1526.64 h60
  text "UL 94V-0" at 11822.96,1526.64 h60
  text "X" at 12498.02,1526.64 h60
  text "RoHS" at 12634.96,1526.64 h60
  text "OTHER" at 13279.36,1526.64 h60
  text "PER ORDER" at 13676.42,1526.64 h60
  text "ADDITIONAL REQUIREMENTS:" at 11332.46,1385.64 h60
  text "MICROSECTION:" at 11407.23,1270.64 h60
  text "YES" at 12312.96,1270.64 h60
  text "REQUIRED" at 13174.46,1114.49 h60
  text "BARE BOARD ELEC. TEST:" at 11407.23,1111.64 h60
  text "NONE" at 12712.96,1111.64 h60
  text "PER ORDER" at 13766.46,1111.64 h60
  text "X" at 13630,1110 h60
  text "MANUFACTURER'S UL:" at 11407.23,954.64 h60
  text "RAIL" at 12572.96,950.35 h60
  text "METAL" at 13064.77,950.35 h60
  text "X" at 13440,950 h60
  text "SILK" at 13576.46,950.35 h60
  text ".Layer_Name" at 577,-858.49 h60
M11 Gerber Information:
  lines w10: -292,-930.17 6308,-930.17 ; -292,-726.83 6310,-726.83 ; -292,-523.5 -292,-1133.5 3713,-1133.5 6310,-1133.5 6310,-523.5 -291.5,-523.5 -291.5,-1133.5 1284,-1133.5 ; 2173,-1133.5 2173,-523.5 ; 3440,-726.83 3440,-523.5 ; 4280,-726.83 4280,-523.5 ; 4902,-1140 4902,-937.17
  text "ALL ARTWORK VIEWED FROM TOP SIDE" at -228.5,-655.67 h60
  text "BOARD #:" at 2248,-655.67 h60
  text ".PRJ_Number" at 2793.5,-655.67 h60
  text "REV:" at 3638,-655.67 h60
  text ".PCB_Rev" at 3929.5,-655.67 h60
  text "SVN REV:" at 4476,-655.67 h60
  text ".VersionControl_RevNumber" at 4982,-655.67 h60
  text "LAYER NAME =" at -228.5,-858.49 h60
  text "PLOT NAME =" at -228.5,-1064.34 h60
  text ".plot_File_Name" at 577,-1064.34 h60
  text "GENERATED    :" at 2250,-1064.34 h60
  text ".Print_Date" at 3119.5,-1064.34 h60
  text ".Print_Time" at 3848.5,-1064.34 h60
  text "TEXAS INSTRUMENTS" at 5113,-1064.34 h60
M12 Stackup:
  lines w6: 11360,7460 13910,7460 ; 11360,7564.4 13910,7564.4 ; 11300,6975 ccw(c11334,6975) 11334,6941 13936,6941 ccw(c13936,6975) 13970,6975 13970,7681 ccw(c13936,7681) 13936,7715 11334,7715 ccw(c11334,7681) 11300,7681 11300,6975
  text "The Stackup Legend below this is static." at 11605.5,7874.5 h60
  text "If you change the stackup, update the Legend." at 11615.5,7784.5 h60
  text "Layer Stack Up Detail for: Ref_Design.PcbDoc" at 11360,7597.1 h57
  text "Layer" at 11360,7525.4 h24
  text "Gerber" at 12255.81,7525.4 h24
  text "Copper" at 12819.33,7525.4 h24
  text "Dielectric" at 13422.04,7525.4 h24
  text "Name" at 11360,7477.4 h24
  text "Document" at 12255.81,7477.4 h24
  text "Thickness" at 12819.33,7477.4 h24
  text "Material" at 13422.04,7477.4 h24
  text "Top Solder Mask" at 11360,7384.44 h34
  text "(.GTS)" at 12255.81,7384.44 h34
  text "Solder Resist" at 13422.04,7384.44 h34
  text "Top Layer" at 11360,7287.69 h34
  text "(.GTL)" at 12255.81,7287.69 h34
  text "1.4mil" at 12819.33,7287.69 h34
  text "FR-4" at 13422.04,7239.31 h34
  text "Bottom Layer" at 11360,7190.94 h34
  text "(.GBL)" at 12255.81,7190.94 h34
  text "1.4mil" at 12819.33,7190.94 h34
  text "Bottom Solder Mask" at 11360,7094.19 h34
  text "(.GBS)" at 12255.81,7094.19 h34
  text "Solder Resist" at 13422.04,7094.19 h34
  text ".Layer_Name" at 577,-858.49 h60
M13 Component Bodies Top:
  text ".Layer_Name" at 577,-858.49 h60
M14 Component Bodies Bottom:
  text ".Layer_Name" at 577,-858.49 h60
M15 Courtyards Top:
  text ".Layer_Name" at 577,-858.49 h60
M16 Courtyards Bottom:
  text ".Layer_Name" at 577,-858.49 h60
Drill Drawing:
  text ".legend" at 4903.2,1167.38 h60
  text "Drill Table" at 4903.2,1041.88 h60
  text ".Layer_Name" at 577,-858.49 h60

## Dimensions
0,0 to 4724.41,0 on M2 Board Dimensions
0,0 to 0,2952.76 on M2 Board Dimensions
